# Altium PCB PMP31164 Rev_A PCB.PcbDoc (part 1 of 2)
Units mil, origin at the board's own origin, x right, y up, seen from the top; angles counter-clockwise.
Board outline 4675 x 1875 mil, 2 copper layers (Top Layer, Bottom Layer), stack 62 mil thick; 52 components, 23 nets, 102 pads, 63 vias.
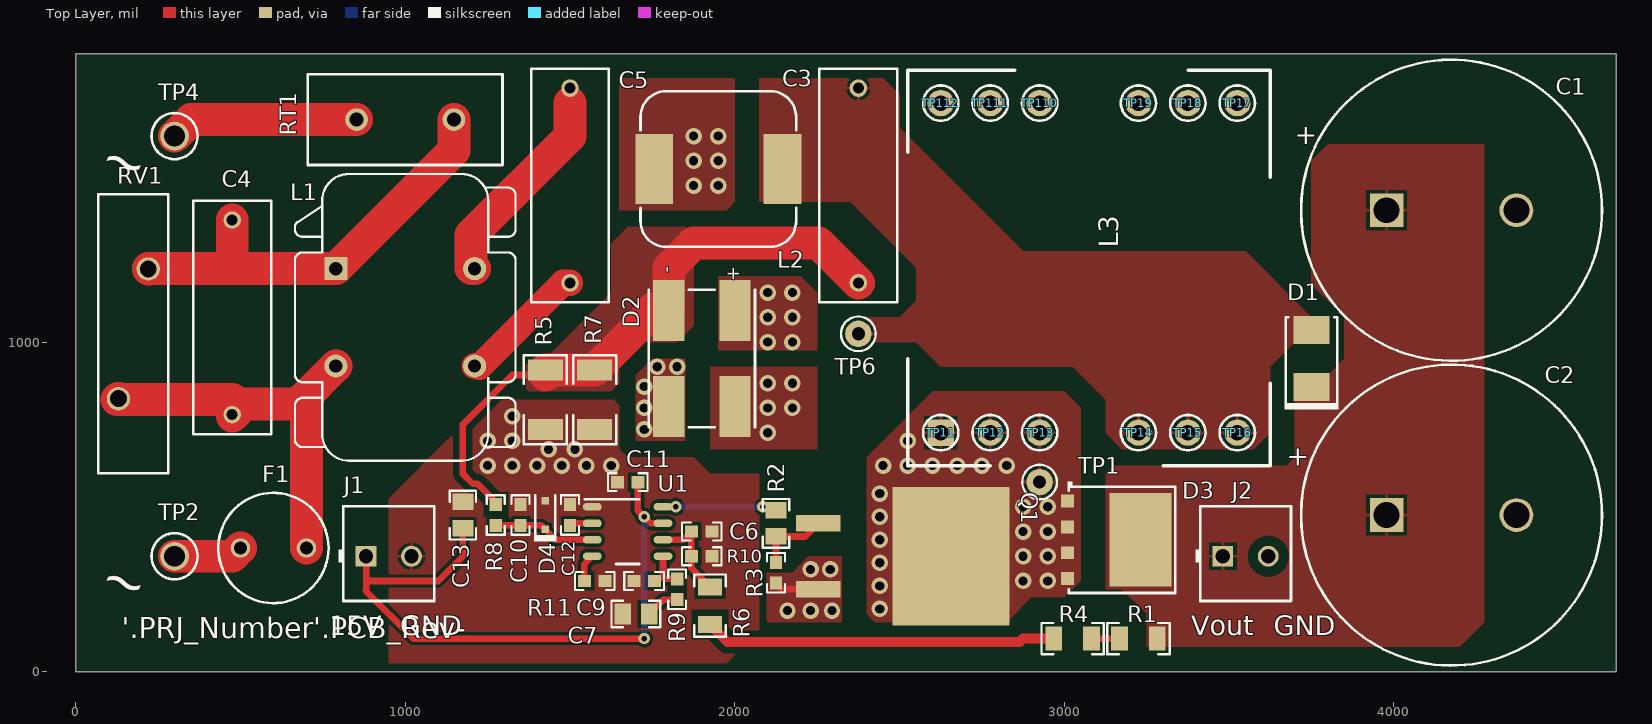
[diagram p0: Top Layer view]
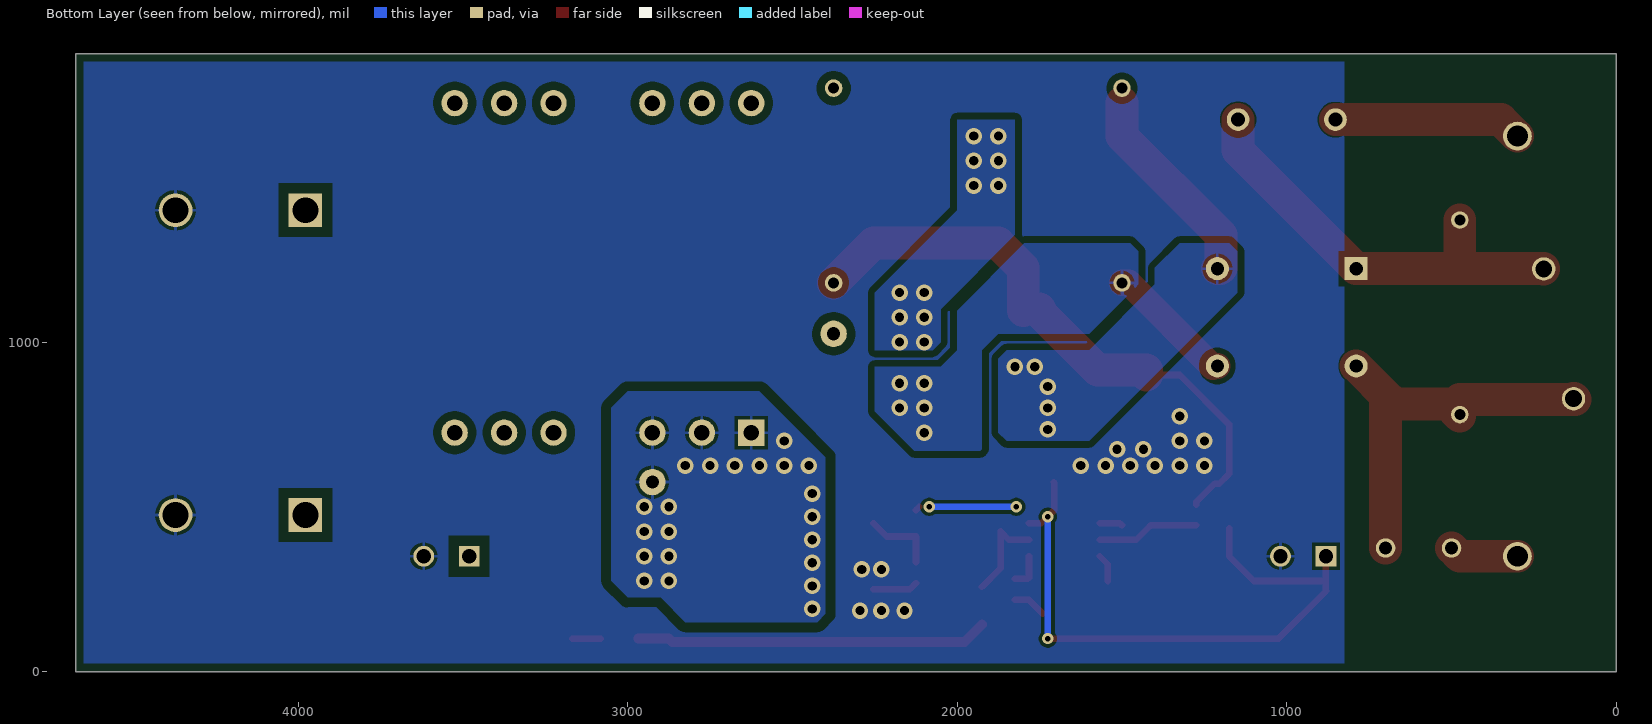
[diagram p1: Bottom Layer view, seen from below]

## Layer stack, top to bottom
Top Solder: solder mask 0.4, Solder Resist, Dk 3.5
Top Layer: signal copper 1.4
Dielectric1: core 59.2, FR-4, Dk 4.8
Bottom Layer: signal copper 1.4
Bottom Solder: solder mask 0.4, Solder Resist, Dk 3.5

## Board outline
0,0 0,1875 4675,1875 4675,0

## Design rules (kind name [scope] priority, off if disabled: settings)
AcuteAngle [All] p1: minimum=4.50000000000000E+0001 checktracksonly=FALSE
AssemblyTestPointUsage [All] p1: valid=2
BoardOutlineClearance BoardOutlineClearance_MountingHoles [OnCopper and InComponentClass('Mounting Holes')] p1: gap=40 ignorepadtopadclearanceinfootprint=FALSE
BoardOutlineClearance BoardOutlineClearance_Poly [OnCopper and IsPoly] p2: gap=25 ignorepadtopadclearanceinfootprint=FALSE
BoardOutlineClearance [OnCopper and Not InComponentClass('Logo') and not InComponentClass('FiducialMark') and not InRegion(1000,500,4000,800) and not InPoly] p3: gap=75 ignorepadtopadclearanceinfootprint=FALSE
Clearance "Schematic Clearance Constraint_21" [InNet('NetC1_1')] p1: gap=30 ignorepadtopadclearanceinfootprint=FALSE except(0: Arc-Hole Track-Hole SMDPad-Hole THPad-Hole Via-Hole Fill-Hole Poly-Hole Region-Hole Text-Hole)
Clearance "Schematic Clearance Constraint_20" [InNet('NetD3_3')] p2: gap=30 ignorepadtopadclearanceinfootprint=FALSE except(0: Arc-Hole Track-Hole SMDPad-Hole THPad-Hole Via-Hole Fill-Hole Poly-Hole Region-Hole Text-Hole)
Clearance "Schematic Clearance Constraint_19" [InNet('NetF1_2')] p3: gap=20 ignorepadtopadclearanceinfootprint=FALSE except(0: Arc-Hole Track-Hole SMDPad-Hole THPad-Hole Via-Hole Fill-Hole Poly-Hole Region-Hole Text-Hole)
Clearance "Schematic Clearance Constraint_18" [InNet('NetC5_2')] p4: gap=30 ignorepadtopadclearanceinfootprint=FALSE
Clearance "Schematic Clearance Constraint_17" [InNet('NetC4_1')] p5: gap=20 ignorepadtopadclearanceinfootprint=FALSE except(0: Arc-Hole Track-Hole SMDPad-Hole THPad-Hole Via-Hole Fill-Hole Poly-Hole Region-Hole Text-Hole)
Clearance "Schematic Clearance Constraint_16" [InNet('NetRT1_1')] p6: gap=20 ignorepadtopadclearanceinfootprint=FALSE except(0: Arc-Hole Track-Hole SMDPad-Hole THPad-Hole Via-Hole Fill-Hole Poly-Hole Region-Hole Text-Hole)
Clearance "Schematic Clearance Constraint_15" [InNet('NetC3_2')] p7: gap=20 ignorepadtopadclearanceinfootprint=FALSE except(0: Arc-Hole Track-Hole SMDPad-Hole THPad-Hole Via-Hole Fill-Hole Poly-Hole Region-Hole Text-Hole)
Clearance "Schematic Clearance Constraint_14" [InNet('NetR4_1')] p8: gap=20 ignorepadtopadclearanceinfootprint=FALSE except(0: Arc-Hole Track-Hole SMDPad-Hole THPad-Hole Via-Hole Fill-Hole Poly-Hole Region-Hole Text-Hole)
Clearance "Schematic Clearance Constraint_13" [InNet('NetC5_1')] p9: gap=30 ignorepadtopadclearanceinfootprint=FALSE
Clearance "Schematic Clearance Constraint_12" [InNet('NetC4_2')] p10: gap=20 ignorepadtopadclearanceinfootprint=FALSE except(0: Arc-Hole Track-Hole SMDPad-Hole THPad-Hole Via-Hole Fill-Hole Poly-Hole Region-Hole Text-Hole)
Clearance "Schematic Clearance Constraint_11" [InNet('NetD2_1')] p11: gap=20 ignorepadtopadclearanceinfootprint=FALSE except(0: Arc-Hole Track-Hole SMDPad-Hole THPad-Hole Via-Hole Fill-Hole Poly-Hole Region-Hole Text-Hole)
Clearance "Schematic Clearance Constraint_10" [InNet('NetR1_1')] p12: gap=20 ignorepadtopadclearanceinfootprint=FALSE except(0: Arc-Hole Track-Hole SMDPad-Hole THPad-Hole Via-Hole Fill-Hole Poly-Hole Region-Hole Text-Hole)
Clearance "Schematic Clearance Constraint_9" [InNet('NetQ1_1')] p13: gap=10 ignorepadtopadclearanceinfootprint=FALSE except(0: Arc-Hole Track-Hole SMDPad-Hole THPad-Hole Via-Hole Fill-Hole Poly-Hole Region-Hole Text-Hole)
Clearance "Schematic Clearance Constraint_8" [InNet('NetC7_1')] p14: gap=10 ignorepadtopadclearanceinfootprint=FALSE except(0: Arc-Hole Track-Hole SMDPad-Hole THPad-Hole Via-Hole Fill-Hole Poly-Hole Region-Hole Text-Hole)
Clearance "Schematic Clearance Constraint_7" [InNet('NetC6_1')] p15: gap=10 ignorepadtopadclearanceinfootprint=FALSE except(0: Arc-Hole Track-Hole SMDPad-Hole THPad-Hole Via-Hole Fill-Hole Poly-Hole Region-Hole Text-Hole)
Clearance "Schematic Clearance Constraint_6" [InNet('NetC3_2')] p16: gap=10 ignorepadtopadclearanceinfootprint=FALSE except(0: Arc-Hole Track-Hole SMDPad-Hole THPad-Hole Via-Hole Fill-Hole Poly-Hole Region-Hole Text-Hole)
Clearance "Schematic Clearance Constraint_5" [InNet('NetR2_1')] p17: gap=10 ignorepadtopadclearanceinfootprint=FALSE except(0: Arc-Hole Track-Hole SMDPad-Hole THPad-Hole Via-Hole Fill-Hole Poly-Hole Region-Hole Text-Hole)
Clearance "Schematic Clearance Constraint_4" [InNet('NetC12_1')] p18: gap=10 ignorepadtopadclearanceinfootprint=FALSE except(0: Arc-Hole Track-Hole SMDPad-Hole THPad-Hole Via-Hole Fill-Hole Poly-Hole Region-Hole Text-Hole)
Clearance "Schematic Clearance Constraint_3" [InNet('NetC11_1')] p19: gap=10 ignorepadtopadclearanceinfootprint=FALSE except(0: Arc-Hole Track-Hole SMDPad-Hole THPad-Hole Via-Hole Fill-Hole Poly-Hole Region-Hole Text-Hole)
Clearance "Schematic Clearance Constraint_2" [InNet('NetR11_2')] p20: gap=10 ignorepadtopadclearanceinfootprint=FALSE except(0: Arc-Hole Track-Hole SMDPad-Hole THPad-Hole Via-Hole Fill-Hole Poly-Hole Region-Hole Text-Hole)
Clearance "Schematic Clearance Constraint_1" [InNet('NetC9_1')] p21: gap=10 ignorepadtopadclearanceinfootprint=FALSE except(0: Arc-Hole Track-Hole SMDPad-Hole THPad-Hole Via-Hole Fill-Hole Poly-Hole Region-Hole Text-Hole)
Clearance "Schematic Clearance Constraint" [InNet('NetC10_1')] p22: gap=10 ignorepadtopadclearanceinfootprint=FALSE except(0: Arc-Hole Track-Hole SMDPad-Hole THPad-Hole Via-Hole Fill-Hole Poly-Hole Region-Hole Text-Hole)
Clearance Clearance_Keepouts [((IsTrack Or IsArc) And Not InPoly) And IsFree and IsKeepOut vs ((IsTrack Or IsArc) And Not InPoly) And IsFree and IsKeepOut] p23: gap=0 ignorepadtopadclearanceinfootprint=FALSE
Clearance Clearance_Poly [InPolygon] p24: gap=25 ignorepadtopadclearanceinfootprint=FALSE except(0: Arc-Hole Track-Hole SMDPad-Hole THPad-Hole Via-Hole Fill-Hole Poly-Hole Region-Hole Text-Hole)
Clearance Clearance_FiducialMark [IsKeepOut and InComponentClass('FiducialMark') vs IsPad and InComponentClass('FiducialMark')] p25: gap=0 ignorepadtopadclearanceinfootprint=FALSE
Clearance [All] p26: gap=7.87 ignorepadtopadclearanceinfootprint=FALSE except(0: Arc-Hole Track-Hole SMDPad-Hole THPad-Hole Via-Hole Fill-Hole Poly-Hole Region-Hole Text-Hole)
ComponentClearance ComponentClearance_MountingHoles_FiducialMarks [InComponentClass('Mounting Holes') vs InComponentClass('FiducialMark')] p1: gap=50 collisioncheckmode=3 verticalgap=10 showdistances=FALSE
ComponentClearance ComponentClearance_Shunt [InComponentClass('Header') vs InComponentClass('Shunt')] p2: gap=0 collisioncheckmode=3 verticalgap=0 showdistances=FALSE
ComponentClearance ComponentClearance_Logo [InComponentClass('Logo')] p3: gap=50 collisioncheckmode=3 verticalgap=10 showdistances=FALSE
ComponentClearance ComponentClearance_ScrewToNut [(HasFootprint('NY PMS 440 0025 PH')) vs (HasFootprint('Keystone_1902C'))] p4: gap=5 collisioncheckmode=3 verticalgap=10 showdistances=FALSE
ComponentClearance ComponentClearance_MountingHoles [InComponentClass('Mounting Holes')] p5: gap=250 collisioncheckmode=3 verticalgap=100000 showdistances=FALSE
ComponentClearance ComponentClearance_SmallPassives [HasFootprint('0201*') or HasFootprint('0402*') or HasFootprint('0508') or HasFootprint('0603*') or HasFootprint('0612') or HasFootprint('0805*') or HasFootprint('0815*') or HasFootprint('0830*') or HasFootprint('1206*') or HasFootprint('1210*') or HasFootprint('1808*') or HasFootprint('1812*') or HasFootprint('1825*') or HasFootprint('2010*') or HasFootprint('2220*') or HasFootprint('2225*') or HasFootprint('2512*') or HasFootprint('2728*') or HasFootprint('3518*') vs HasFootprint('0201*') or HasFootprint('0402*') or HasFootprint('0508') or HasFootprint('0603*') or HasFootprint('0612') or HasFootprint('0805*') or HasFootprint('0815*') or HasFootprint('0830*') or HasFootprint('1206*') or HasFootprint('1210*') or HasFootprint('1808*') or HasFootprint('1812*') or HasFootprint('1825*') or HasFootprint('2010*') or HasFootprint('2220*') or HasFootprint('2225*') or HasFootprint('2512*') or HasFootprint('2728*') or HasFootprint('3518*')] p6: gap=14.96 collisioncheckmode=3 verticalgap=10 showdistances=FALSE
ComponentClearance ComponentClearance_THtoSMT [IsThruComponent vs IsSMTComponent] p7: gap=40 collisioncheckmode=3 verticalgap=30 showdistances=FALSE
ComponentClearance ComponentClearance_THtoTH [IsThruComponent vs IsThruComponent] p8: gap=30 collisioncheckmode=3 verticalgap=30 showdistances=FALSE
ComponentClearance [All] p9: gap=30 collisioncheckmode=3 verticalgap=10 showdistances=FALSE
DiffPairsRouting [All] p1: maxlimit=100 minlimit=10 mostfreqgap=10 toplayer_minwidth=15 toplayer_maxwidth=15 toplayer_prefwidth=15 bottomlayer_minwidth=15 bottomlayer_maxwidth=15 bottomlayer_prefwidth=15 maxuncoupledlength=1000
FabricationTestPointUsage TestPointUsage [All] p1: valid=2 allowmultiple=FALSE
FabricationTestpoint Testpoint [All] p1: side=3 testpointundercomponent=TRUE minsize=40 maxsize=100 preferedsize=60 minholesize=0 maxholesize=40 preferedholesize=32 testpointgrid=1 allowsidetop=TRUE allowsidebottom=TRUE usegrid=TRUE gridtolerance=0.01
FanoutControl Fanout_LCC [IsLCC] p1: bgadir=Out bgaviamode=Centered fanoutstyle=Auto fanoutdirection=Alternating viagrid=1 // Fanout_LCC (Default Rule)
FanoutControl Fanout_BGA [IsBGA] p2: bgadir=Out bgaviamode=Centered fanoutstyle=Auto fanoutdirection=Alternating viagrid=1 // Fanout_BGA (Default Rule)
FanoutControl Fanout_Default [All] p4: bgadir=Out bgaviamode=Centered fanoutstyle=Auto fanoutdirection=Alternating viagrid=1 // Fanout_Default (Default Rule)
FanoutControl Fanout_Small [(CompPinCount < 5)] p5: bgadir=Out bgaviamode=Centered fanoutstyle=Auto fanoutdirection=OutThenIn viagrid=1 // Fanout_Small (Default Rule)
HoleSize [All] p1: absolutevalues=TRUE maxlimit=251 minlimit=7.87 maxpercent=80.000 minpercent=20.000
MinimumAnnularRing MinimumAnnularRing_ThermalPadVias [IsVia and InAnyComponent] p1: minimumring=5.91
MinimumAnnularRing [All] p2: minimumring=8
MinimumSolderMaskSliver MinimumSolderMaskSliver_Logo [InComponentClass('Logo') vs InComponentClass('Logo')] p1: minsoldermaskwidth=0.7
MinimumSolderMaskSliver [All] p2: minsoldermaskwidth=3.94
PlaneConnect [All] p1: pad.planeconnectstyle=Relief pad.reliefexpansion=10 pad.reliefentries=4 pad.reliefconductorwidth=10 pad.reliefairgap=10 via.planeconnectstyle=Direct via.reliefexpansion=10 via.reliefentries=4 via.reliefconductorwidth=10 via.reliefairgap=10
PolygonConnect [All] p1: thpad.connectstyle=Relief thpad.reliefconductorwidth=10 thpad.reliefentries=4 thpad.polygonreliefangle="90 Angle" thpad.airgapwidth=10 smdpad.connectstyle=Direct smdpad.reliefconductorwidth=10 smdpad.reliefentries=4 smdpad.polygonreliefangle="90 Angle" smdpad.airgapwidth=10 via.connectstyle=Direct via.reliefconductorwidth=10 via.reliefentries=4 via.polygonreliefangle="90 Angle" via.airgapwidth=10
RoomDefinition "PMP31164 Rev_A Schematic" [InComponentClass('PMP31164 Rev_A Schematic')] p1: confinementstyle=ConfineIn formatcopy=TRUE lockcomponents=FALSE outline 4998,66 10550,66 10550,1106 4998,1106
RoutingVias ThermalPadVias [IsVia and InAnyComponent] p1: holewidth=7.87 width=19.68 viastyle="Through Hole" minholewidth=7.87 minwidth=19.68 maxholewidth=12.99 maxwidth=23.62
RoutingVias [All] p2: holewidth=16 width=34 viastyle="Through Hole" minholewidth=7.87 minwidth=26 maxholewidth=40 maxwidth=65
SilkToBoardRegionClearance [Not ((IsComment or IsDesignator) And (Hide <> 'False')) and not InRegion(1000,500,4000,800)] p1:
SilkToSilkClearance SilkToSilkClearance_Pb-FreeLogo [(HasFootprint('Pb-Free_Overlay_Medium') OR HasFootprint('Pb-Free_Overlay_Small')) vs (HasFootprint('Pb-Free_Overlay_Medium') OR HasFootprint('Pb-Free_Overlay_Small'))] p1: silktosilkclearance=0
SilkToSilkClearance [All] p2: silktosilkclearance=4
SilkToSolderMaskClearance SilkToComponentPadClearance [(IsPad or IsFill or IsRegion) and InAnycomponent] p1: minsilkscreentomaskgap=5 clearancetoexposedcopper=TRUE
SilkToSolderMaskClearance "Silk to Solder Mask Opening" [All] p2: minsilkscreentomaskgap=4 clearancetoexposedcopper=FALSE
SolderMaskExpansion [All] p1: expansion=1.97 istentingtop=FALSE
Width [All] p1: maxlimit=100 minlimit=6 preferedwidth=10 checkconnectedcopper=TRUE
15 further rules are at their usual default settings.

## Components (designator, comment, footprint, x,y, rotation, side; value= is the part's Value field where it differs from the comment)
C1 "ESMQ451VSN101MP25S" SMQ_2200X2500 4175,1400 r0 top value=100uF
C2 "ESMQ451VSN101MP25S" SMQ_2200X2500 4175,475 r0 top value=100uF
C3 "ECQ-U2A104ML" CAPRR1500W60L1750T550H1250 2375,1475 r270 top value=0.1uF
C4 "ECQ-U2A104ML" CAPRR1500W60L1750T550H1250 475,1075 r90 top value=0.1uF
C5 "ECQ-U2A104ML" CAPRR1500W60L1750T550H1250 1500,1475 r90 top value=0.1uF
C6 "C0603C102K5RACTU" 0603 1900,425 r0 top value=1000pF
C7 "C2012X5R1E475K125AB" 0805_HV 1700,175 r180 top value=4.7uF
C9 "06033C473JAT2A" 0603 1725,275 r180 top value=0.047uF
C10 "C0603C102K5RACTU" 0603 1350,475 r90 top value=1000pF
C11 "C1608X7R1H104K080AA" 0603 1675,575 r180 top value=0.1uF
C12 "C0603C222K5RACTU" 0603 1500,475 r90 top value=2200pF
C13 "C2012X5R1E475K125AB" 0805_HV 1175,475 r90 top value=4.7uF
D1 "S3JB-13-F" SMB 3750,950 r90 top
D2 "Z4DGP406L-HF" Z4-D 1900,950 r270 top value=600V
D3 "IDL02G65C5XUMA1" PG-VSON-4 3175,400 r270 top value=650V
D4 "BAS20HT1G" SOD-323 1425,475 r90 top value=200V
F1 "37213150001" FUSE_372 600,375 r180 top
J1 "39357-0002" MOLEX_39357-0002 950,350 r0 top
J2 "39357-0002" MOLEX_39357-0002 3550,350 r0 top
L1 "744823210" WE-CMB_M 1000,1075 r0 top value=10mH
L2 "7447709101" WE-PD_1210 1950,1525 r0 top value=100uH
Q1 "IPB65R225C7ATMA1" DDPAK 2500,350 r0 top value=IPB65R225C7
R1 "RC1206FR-07330KL" 1206 3225,100 r0 top value=330k
R2 "CRCW08052R21FKEA" 0805_HV 2125,450 r270 top value=2.21
R3 "CRCW060310K0FKEA" 0603 2125,300 r90 top value=10.0k
R4 "RC1206FR-07330KL" 1206 3025,100 r0 top value=330k
R5 "CSRN2010FKR300" 2010 1425,825 r270 top value=0.3
R6 "RC1206FR-07330KL" 1206 1925,200 r270 top value=330k
R7 "CSRN2010FKR300" 2010 1575,825 r270 top value=0.3
R8 "CRCW0603221RFKEA" 0603 1275,475 r90 top value=221
R9 "RC0603FR-0747KL" 0603 1825,250 r90 top value=47.0k
R10 "CRCW060314K0FKEA" 0603 1900,350 r180 top value=14.0k
R11 "CRCW060314K7FKEA" 0603 1575,275 r180 top value=14.7k
RT1 "B57237S0479M000" S237 1000,1675 r0 top value=4.7
RV1 "B72220S0271K101" Epcos_B72220S0271K101 175,1025 r270 top value=275VAC
TP1 "5000" Keystone5000 2925,575 r0 top
TP2 "5012" Keystone5012 300,350 r0 top
TP4 "5012" Keystone5012 300,1625 r0 top
TP6 "5000" Keystone5000 2375,1025 r90 top
TP11 "1" TESTPOINT#1 2625,725 r90 top
TP12 "2" TESTPOINT#2 2775,725 r180 top
TP13 "3" TESTPOINT#2 2925,725 r180 top
TP14 "4" TESTPOINT#2 3225,725 r180 top
TP15 "5" TESTPOINT#2 3375,725 r180 top
TP16 "6" TESTPOINT#2 3525,725 r180 top
TP17 "7" TESTPOINT#2 3525,1725 r180 top
TP18 "8" TESTPOINT#2 3375,1725 r180 top
TP19 "9" TESTPOINT#2 3225,1725 r180 top
TP110 "10" TESTPOINT#2 2925,1725 r180 top
TP111 "11" TESTPOINT#2 2775,1725 r180 top
TP112 "12" TESTPOINT#2 2625,1725 r180 top
U1 "UCC28180DR" D0008A_N 1675,425 r0 top

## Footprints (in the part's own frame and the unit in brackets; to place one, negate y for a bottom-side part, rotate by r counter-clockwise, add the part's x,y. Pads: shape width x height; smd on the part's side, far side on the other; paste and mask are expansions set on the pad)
0603 [mm] "0603 from SM-752 data"
  rect 1x0.95 smd: 1(-0.8,0) 2(0.8,0)
  silkscreen extent -1.52,-0.69 1.52,0.69, body extent -0.87,-0.47 0.87,0.47, height 1
0805_HV [mil] "0805 with 30mil clearance between pads"
  rect 50x63 smd: 1(-40,0) 2(40,0)
  silkscreen extent -74,-40 74,40, body extent -43,-29 43,29, height 57
1206 [mm] "1206 from SM-752 data"
  rect 1.3x1.85 smd: 1(-1.45,0) 2(1.45,0)
  silkscreen extent -2.4,-1.21 2.4,1.21, body extent -1.7,-0.9 1.7,0.9, height 1.35
2010 [mm] "Chip Capacitor, Body 5.08x2.54mm, IPC Medium Density"
  rect 1.6x2.7 smd: 1(-2.3,0) 2(2.3,0)
  silkscreen extent -3.42,-1.65 3.42,1.65, body extent -2.73,-1.45 2.73,1.45, height 1.66
CAPRR1500W60L1750T550H1250 [mm] "PANASONIC"
  round 1.35 hole 0.85: 1(-7.5,0) 2(7.5,0)
  silkscreen extent -9,-3 9,3, body extent -9.05,-3.05 9.05,3.05, height 13
D0008A_N [mm] "SOIC, 8-Leads, Body 4.9x3.9mm, Pitch 1.27mm, IPC Medium Density"
  oval 1.45x0.6 smd: 1(-2.725,1.905) 2(-2.725,0.635) 3(-2.725,-0.635) 4(-2.725,-1.905) 5(2.725,-1.905) 6(2.725,-0.635) 7(2.725,0.635) 8(2.725,1.905)
  silkscreen extent -3.3,-2.5 0.9,2.5, body extent -3,-2.45 3,2.45, height 1.63
DDPAK [mil] "D2-PAK, 3-Pads, Body 9.7x10.4mm (max), TO-263AB, using Vishay Silionix recommended pad sizes"
  rrect8% 135x49.49 smd: 1(-246.06,100) 3(-246.06,-100)
  rrect1% 355x420 smd paste-181.1: 2(155.51,0)
  body extent -295,-202 324,202, height 180
Epcos_B72220S0271K101 [mm] "TH, 2-Leads, Dia 21.5mm, Pin Spacing 10mm"
  round 1.8 hole 1.3: 1(-5,1.15) 2(5,-1.15)
  silkscreen extent -10.75,-2.7 10.75,2.7, body extent -10.66,-2.7 10.75,2.7, height 25.48
FUSE_372 [mm] "LITTELFUSE"
  round 1.5 hole 1: 1(-2.54,0) 2(2.54,0)
  silkscreen extent -4.25,-4.25 4.25,4.25, body extent -4.25,-4.25 4.25,4.25, height 8
Keystone5000 [mil] "For Keystone 500x miniature loop terminals"
  round 80 hole 40: 1(0,0)
  silkscreen extent -52,-52 52,52, body extent -49,-49 49,49, height 182
Keystone5012 [mil] "Keystone Multipurpose loops"
  round 87 hole 63: 1(0,0)
  silkscreen extent -70,-70 70,70, body extent -63,-63 63,62, height 319
MOLEX_39357-0002 [mm] "Terminal Block, 3.5 mm, 2x1, TH"
  rect 1.6x1.6 hole 1.1: 1(-1.75,0)
  round 1.6 hole 1.1: 2(1.75,0)
  silkscreen extent -3.86,-3.45 3.5,3.84, body extent -3.55,-3.45 3.56,3.84, height 8.51
PG-VSON-4 [mm] "INFINEON TECHNOLOGIES"
  rect 1x1 smd: 1(-3,-4.2) 2(-1,-4.2) 3(1,-4.2) 4(3,-4.2)
  rect 7.2x4.75 smd: 5(0,1.43)
  silkscreen extent -4.5,-4.2 4.1,4.1, body extent -4.05,-4.05 4.05,4.05, height 1.1
S237 [mm] "EPCOS"
  round 1.75 hole 1.1: 1(-3.75,0) 2(3.75,0)
  silkscreen extent -7.5,-3.5 7.5,3.5, body extent -7.47,-3.5 7.47,3.5, height 21.99
SMB [mil] "Molded Diode, 2-Leads, Body 5.4x3.6mm, IPC Medium Density, based on OnSemi component dimensions"
  rect 85x107.99 smd: 1(-87.01,0) 2(87.01,0)
  silkscreen extent -155,-82 125,82, body extent -106,-71 106,71, height 91
SMQ_2200X2500 [mm] "United Chemi-Con Inc"
  rect 2.6x2.6 hole 2: 1(-5,0)
  round 2.6 hole 2: 2(5,0)
  silkscreen extent -11.6,-11.6 11.6,11.6, body extent -11.41,-11.48 11.47,11.48, height 27.01
SOD-323 [mm] "NXP recommended land pattern"
  rect 0.6x0.6 smd paste-0.05: 1(-1.1,0) 2(1.1,0)
  silkscreen extent -2.06,-0.86 1.53,0.86, body extent -1.3,-0.67 1.3,0.68, height 1.1
TESTPOINT#1 [mil]
  rect 80x80 hole 47.24: 1(0,0)
  silkscreen extent -53,-54 53,54
TESTPOINT#2 [mil]
  round 80 hole 47.24: 1(0,0)
  silkscreen extent -54,-53 54,53
WE-CMB_M [mil] "Wurth"
  rect 70x70 hole 40: 1(-210.63,147.64)
  round 70 hole 40: 2(-210.63,-147.64) 3(210.63,-147.64) 4(210.63,147.64)
  silkscreen extent -335,-435 335,435, body extent -335,-394 335,394, height 1044
WE-PD_1210 [mm] "Wurth Elektronik recommended land pattern"
  rect 2.9x5.4 smd: 1(-4.95,0) 2(4.95,0)
  silkscreen extent -6,-6 6,6, body extent -6,-6 6,6, height 10.01
Z4-D [mm] "SMD, 4-Leads, Body 8.1x10.5mm"
  rect 4.7x2.4 smd: 1(-3.7,2.55) 2(3.7,2.55) 3(3.7,-2.55) 4(-3.7,-2.55)
  silkscreen extent -5.3,-4.1 5.3,4.1, body extent -5.3,-4.1 5.3,4.1, height 1.56

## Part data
C1 C2: library part CMP-0010054-2, "CAP, AL, 100 uF, 450 V, +/- 20%, TH", Cap_Case=22x25, Manufacturer=Chemi-Con, Supplier Part Number 1=565-2785-ND, Tolerance_%=20%, Value1=Unknown, Value2=450V, ValueDisplayed=100uF
C3 C4 C5: library part CMP-0012496-3, "CAP, Film, 0.1 uF, 275 V, +/- 20%, TH", Cap_Case="Radial 17.5x5.5x12.5", Manufacturer=Panasonic, Supplier Part Number 1=P10730-ND, Tolerance_%=20%, Value1=Unknown, Value2=275V, ValueDisplayed=0.1uF
C6: library part CMP-0006847-4, "CAP, CERM, 1000 pF, 50 V, +/- 10%, X7R, 0603", Cap_Case=0603, Manufacturer=Kemet, Supplier Part Number 1=399-1082-1-ND, TempCo=X7R, Tolerance_%=10%, Value1=Unknown, Value2=50V, ValueDisplayed=1000pF
C7 C13: library part CMP-0007829-2, "CAP, CERM, 4.7 uF, 25 V, +/- 10%, X5R, 0805", Cap_Case=0805, Manufacturer=TDK, Supplier Part Number 1=445-4116-1-ND, TempCo=X5R, Tolerance_%=10%, Value1=Unknown, Value2=25V, ValueDisplayed=4.7uF
C9: library part CMP-0006757-5, "CAP, CERM, 0.047 uF, 25 V, +/- 5%, X7R, 0603", Cap_Case=0603, Manufacturer=AVX, Supplier Part Number 1=478-3716-1-ND, TempCo=X7R, Tolerance_%=5%, Value1="0.052 ohm", Value2=25V, ValueDisplayed=0.047uF
C10: library part CMP-0007229-4, "CAP, CERM, 680 pF, 50 V, +/- 5%, C0G/NP0, 0603", Cap_Case=0603, Manufacturer=Kemet, Supplier Part Number 1=399-1082-1-ND, TempCo=X7R, Tolerance_%=10%, Value1=Unknown, Value2=50V, ValueDisplayed=1000pF
C11: library part CMP-0007044-5, "CAP, CERM, 0.1 uF, 50 V, +/- 10%, X7R, 0603", Cap_Case=0603, Manufacturer=TDK, Supplier Part Number 1=445-1314-1-ND, TempCo=X7R, Tolerance_%=10%, Value1="0.0296 ohm", Value2=50V, ValueDisplayed=0.1uF
C12: library part CMP-0007186-4, "CAP, CERM, 1500 pF, 50 V, +/- 5%, C0G/NP0, 0603", Cap_Case=0603, Manufacturer=Kemet, Supplier Part Number 1=399-1085-1-ND, TempCo=X7R, Tolerance_%=10%, Value1=Unknown, Value2=50V, ValueDisplayed=2200pF
D1: library part CMP-0076890-2, "Diode, Standard, 600 V, 3 A, SMB", Manufacturer="Diodes Inc.", Value1=3A, Value2=0.92V
D2: library part CMP-0029244-3, "Diode, P-N-Bridge, 600 V, 4 A, Z4-D", Manufacturer="Comchip Technology", Value1=4A, Value2=0.95V
D3: library part CMP-0076996-2, "Diode, Schottky, 650 V, 2 A, PG-VSON-4", Manufacturer="Infineon Technologies", Value1=2A, Value2=1.7V
D4: library part CMP-0029150-2, "Diode, Switching, 200 V, 0.2 A, AEC-Q101, SOD-323", Manufacturer="ON Semiconductor", Value1=0.2A, Value2=1.25V
F1: library part CMP-0003557-2, "Fuse, 3.15 A, 250VAC/VDC, TH", Irating_A=3.15A, Manufacturer=Littelfuse, Supplier Part Number 1=WK4224CT-ND
J1 J2: library part CMP-0055341-1, "Terminal Block, 3.5 mm, 2x1, Tin, TH", Manufacturer=Molex, Supplier Part Number 1=WM7877-ND
L1: library part CMP-0076828-1, "Coupled inductor, 10 mH, 2 A, 0.125 ohm, TH", Manufacturer="Wurth Elektronik", Supplier Part Number 1=732-1447-ND, ValueDisplayed=10mH
L2: library part CMP-0064536-2, "Inductor, Shielded Drum Core, Ferrite, 100 uH, 2.5 A, 0.1 ohm, SMD", Manufacturer="Wurth Elektronik", Supplier Part Number 1=732-1248-1-ND, Value1="0.1 ohm", Value2=2.5A, ValueDisplayed=100uH
Q1: library part CMP-0081192-2, "MOSFET, N-CH, 650 V, 56 A, DDPAK", Alternate Manufacturer=None, Manufacturer="Infineon Technologies", Supplier Part Number 1=IPB65R225C7ATMA1CT-ND, Value1="? ohm", Value2="20 nC"
R1 R4 R6: library part CMP-0018205-2, "RES, 330 k, 1%, 0.25 W, 1206", Manufacturer="Yageo America", Power_W=250mW, Supplier Part Number 1=311-330KFRCT-ND, TempCo="100 ppm/C", Tolerance_%=1%, Value2=0.25W, Value_Code=330k
R2: library part CMP-0021145-3, "RES, 2.21, 1%, 0.125 W, AEC-Q200 Grade 0, 0805", Manufacturer=Vishay-Dale, Power_W=125mW, Supplier Part Number 1=541-2.21CCCT-ND, TempCo="100 ppm/C", Tolerance_%=1%, Value2=0.125W, Value_Code=2R21, ValueDisplayed=2.21
R3: library part CMP-0021998-4, "RES, 10.0 k, 1%, 0.1 W, AEC-Q200 Grade 0, 0603", Manufacturer=Vishay-Dale, Power_W=100mW, Supplier Part Number 1=541-10.0KHCT-ND, TempCo="100 ppm/C", Tolerance_%=1%, Value2=0.1W, Value_Code=10k0, ValueDisplayed=10.0k
R5 R7: library part CMP-0016526-2, "RES, 0.25, 1%, 1 W, 2010", Manufacturer="Stackpole Electronics Inc", Power_W=1W, Supplier Part Number 1=CSRN2010FKR300CT-ND, TempCo="250 ppm/C", Tolerance_%=1%, Value_Code=R300, ValueDisplayed=0.3
R8: library part CMP-0022217-5, "RES, 221, 1%, 0.1 W, AEC-Q200 Grade 0, 0603", Manufacturer=Vishay-Dale, Power_W=100mW, Supplier Part Number 1=541-221HCT-ND, TempCo="100 ppm/C", Tolerance_%=1%, Value2=0.1W, Value_Code=221R, ValueDisplayed=221
R9: library part CMP-0023133-5, "RES, 47.0 k, 1%, 0.1 W, 0603", Manufacturer=Yageo, Power_W=100mW, Supplier Part Number 1=311-47.0KHRCT-ND, TempCo="100 ppm/C", Tolerance_%=1%, Value2=0.1W, Value_Code=47k0, ValueDisplayed=47.0k
R10: library part CMP-0022054-4, "RES, 14.0 k, 1%, 0.1 W, AEC-Q200 Grade 0, 0603", Manufacturer=Vishay-Dale, Power_W=100mW, Supplier Part Number 1=541-14.0KHCT-ND, TempCo="100 ppm/C", Tolerance_%=1%, Value2=0.1W, Value_Code=14k0, ValueDisplayed=14.0k
R11: library part CMP-0022816-5, "RES, 15.0 k, 1%, 0.1 W, 0603", Manufacturer=Vishay-Dale, Power_W=100mW, Supplier Part Number 1=541-14.7KHCT-ND, TempCo="100 ppm/C", Tolerance_%=1%, Value2=0.1W, Value_Code=14k7, ValueDisplayed=14.7k
RT1: library part CMP-0002554-2, "Thermistor NTC, 4.70 ohm, 20%, 15x7mm", Manufacturer=TDK, Power_W=3.1W, Supplier Part Number 1=495-2099-ND, Tolerance_%=20%
RV1: library part CMP-0001856-2, "Varistor 275 VAC, 100 A, TH", Manufacturer=TDK, Supplier Part Number 1=96K7679
TP1 TP6: library part CMP-0055137-2, "Test Point, Miniature, Red, TH", Color=Red, Manufacturer="Keystone Electronics", Supplier Part Number 1=36-5000-ND
TP2 TP4: library part CMP-0055149-2, "Test Point, Multipurpose, White, TH", Color=White, Manufacturer="Keystone Electronics", Supplier Part Number 1=36-5012-ND
TP11 TP12 TP13 TP14 TP15 TP16 TP17 TP18 TP19 TP110 TP111 TP112: library part CMP-0078143-3, "TEST POINT.  No entry in BOM.", Manufacturer=N/A
U1: library part CMP-0074100-1, "8-PIN CONTINUOUS CONDUCTION MODE (CCM) PFC CONTROLLER, D0008A (SOIC-8)", Alternate Manufacturer="Texas Instruments", Alternate PartNumber=UCC28180D

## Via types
v1: diameter 50, hole 28, Top Layer to Bottom Layer, 59 vias
v2: diameter 34, hole 16, Top Layer to Bottom Layer, 4 vias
